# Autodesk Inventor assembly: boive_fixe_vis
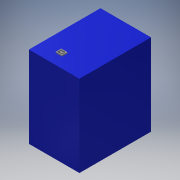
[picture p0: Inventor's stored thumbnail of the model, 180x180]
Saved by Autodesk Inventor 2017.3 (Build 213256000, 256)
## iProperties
Part Number: boive_fixe_vis
Material: Générique
Document SubType Name: Assembly
Designer: ficho
Author: ficho
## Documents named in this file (8)
- G:\travail\année 2019-2020\réforme\avant février\IT\boive_fixe_vis.iam
- G:\travail\année 2019-2020\réforme\avant février\IT\flanc2_boite_vis.ipt
- G:\travail\année 2019-2020\réforme\avant février\IT\fond_boite_vis.ipt
- G:\travail\année 2019-2020\réforme\avant février\IT\dessus_boite_vis.ipt
- G:\travail\année 2019-2020\réforme\avant février\IT\corps moto reducteur.ipt
- G:\travail\année 2019-2020\réforme\avant février\IT\arduino uno et shield.iam
- G:\travail\année 2019-2020\réforme\avant février\IT\Porte_arduino.ipt
- G:\travail\année 2019-2020\réforme\avant février\IT\Porte_moteur.ipt
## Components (9 placed, 7 different names)
1. flanc2_boite_vis:1 — Affleurement:2, Affleurement:5, Affleurement:7, Affleurement:9, Affleurement:10
2. fond_boite_vis:1 — Affleurement:11, Affleurement:12, Affleurement:13, Placage:1, Placage:2, Affleurement:18, Placage:3
3. flanc2_boite_vis:2 — Affleurement:1, Affleurement:2, Affleurement:3, Affleurement:4, Affleurement:8, Affleurement:12, Affleurement:14, Affleurement:17
4. dessus_boite_vis:1 — Affleurement:1, Affleurement:7, Affleurement:10
5. dessus_boite_vis:2 — Affleurement:3, Affleurement:4, Affleurement:5, Affleurement:8, Affleurement:9, Affleurement:11, Affleurement:13, Affleurement:14, Affleurement:15, Affleurement:16
6. corps moto reducteur:1 — Placage:1, Logement:1
7. arduino uno et shield:1 [sub-assembly] — Placage:2, Affleurement:15
8. Porte_arduino:1 — Affleurement:17, Affleurement:18, Placage:3
9. Porte_moteur:1 — Logement:1, Affleurement:16
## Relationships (21: Flush 17, Mate 3, Insert 1)
- Affleurement:1 [Flush]: flanc2_boite_vis:2 ↔ dessus_boite_vis:1
- Affleurement:2 [Flush]: flanc2_boite_vis:1 ↔ flanc2_boite_vis:2
- Affleurement:3 [Flush]: flanc2_boite_vis:2 ↔ dessus_boite_vis:2
- Affleurement:4 [Flush]: flanc2_boite_vis:2 ↔ dessus_boite_vis:2
- Affleurement:5 [Flush]: flanc2_boite_vis:1 ↔ dessus_boite_vis:2
- Affleurement:7 [Flush]: flanc2_boite_vis:1 ↔ dessus_boite_vis:1
- Affleurement:8 [Flush]: flanc2_boite_vis:2 ↔ dessus_boite_vis:2
- Affleurement:9 [Flush]: flanc2_boite_vis:1 ↔ dessus_boite_vis:2
- Affleurement:10 [Flush]: flanc2_boite_vis:1 ↔ dessus_boite_vis:1
- Affleurement:11 [Flush]: fond_boite_vis:1 ↔ dessus_boite_vis:2
- Affleurement:12 [Flush]: fond_boite_vis:1 ↔ flanc2_boite_vis:2
- Affleurement:13 [Flush]: fond_boite_vis:1 ↔ dessus_boite_vis:2
- Affleurement:14 [Flush]: flanc2_boite_vis:2 ↔ dessus_boite_vis:2
- Placage:1 [Mate]: fond_boite_vis:1 ↔ corps moto reducteur:1
- Placage:2 [Mate]: fond_boite_vis:1 ↔ arduino uno et shield:1
- Affleurement:15 [Flush]: dessus_boite_vis:2 ↔ arduino uno et shield:1
- Logement:1 [Insert]: corps moto reducteur:1 ↔ Porte_moteur:1
- Affleurement:16 [Flush]: dessus_boite_vis:2 ↔ Porte_moteur:1
- Affleurement:17 [Flush]: flanc2_boite_vis:2 ↔ Porte_arduino:1
- Affleurement:18 [Flush]: fond_boite_vis:1 ↔ Porte_arduino:1
- Placage:3 [Mate]: fond_boite_vis:1 ↔ Porte_arduino:1
